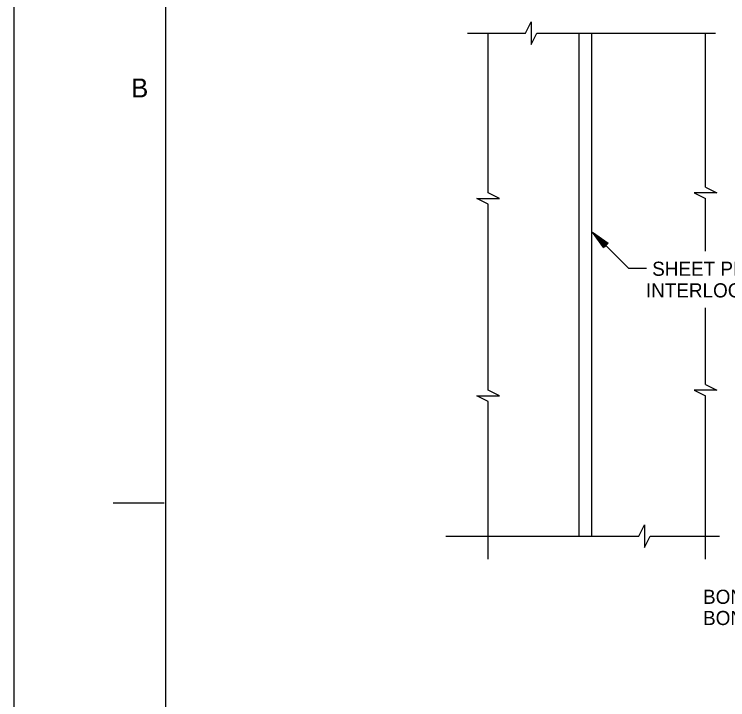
# Model space of a CAD drawing. Extents: x 22369.6 to 22428.3, y 22369.6 to 22415.
# Drawn here: x 22369.62 to 22379.05, y 22378.68 to 22387.74 of the extents above; entities that cross this region are included whole.
import ezdxf

# ---------------------------------------------------------------- set-up
doc = ezdxf.new("R2010")
doc.units = 0
for name, color, linetype in [('Level 1', 7, 'Continuous'), ('Level 10', 7, 'Continuous'), ('Level 2', 7, 'Continuous'), ('Level 3', 7, 'Continuous'), ('Level 4', 7, 'Continuous'), ('Level 9', 7, 'Continuous')]:
    doc.layers.add(name, color=color, linetype=linetype)

msp = doc.modelspace()

# ---------------------------------------------------------------- linework, layer by layer
at = {"layer": 'Level 1'}
for p, q in [((22375.6089, 22387.4886), (22376.3752, 22387.4886)), ((22375.8823, 22385.3773), (22375.8823, 22387.4886)), ((22376.5247, 22387.4886), (22378.8846, 22387.4886)), ((22378.7536, 22385.452), (22378.7536, 22387.4886)), ((22378.7536, 22384.6093), (22378.7536, 22385.3025)), ((22375.8823, 22382.7706), (22375.8823, 22385.2278)), ((22378.7536, 22382.8454), (22378.7536, 22383.86)), ((22375.8823, 22380.5372), (22375.8823, 22382.6211)), ((22378.7536, 22380.5372), (22378.7536, 22382.6959)), ((22375.3239, 22380.8406), (22377.8724, 22380.8406)), ((22378.0219, 22380.8406), (22378.9382, 22380.8406))]:
    msp.add_line(p, q, dxfattribs=at)
msp.add_lwpolyline([(22369.6213, 22414.9546), (22428.2885, 22414.9546), (22428.2885, 22369.6213), (22369.6213, 22369.6213)], close=True, dxfattribs=at)
for points in [[(22376.3752, 22387.4886), (22376.4497, 22387.6386), (22376.4497, 22387.339), (22376.5247, 22387.4886)], [(22378.7536, 22385.452), (22378.9036, 22385.3775), (22378.604, 22385.3775), (22378.7536, 22385.3025)], [(22375.8823, 22385.2278), (22375.7323, 22385.3023), (22376.032, 22385.3023), (22375.8823, 22385.3773)], [(22377.9726, 22384.3797), (22377.74, 22384.3797), (22377.261, 22384.8594)], [(22378.7536, 22382.8454), (22378.9036, 22382.7709), (22378.604, 22382.7709), (22378.7536, 22382.6959)], [(22375.8823, 22382.6211), (22375.7323, 22382.6956), (22376.032, 22382.6956), (22375.8823, 22382.7706)], [(22377.8724, 22380.8406), (22377.9469, 22380.9906), (22377.9469, 22380.6909), (22378.0219, 22380.8406)]]:
    msp.add_lwpolyline(points, dxfattribs=at)
at = {"layer": 'Level 10'}
msp.add_line((22370.9285, 22381.28), (22371.6005, 22381.28), dxfattribs=at)
at = {"layer": 'Level 2'}
for p, q in [((22377.0811, 22387.4886), (22377.0811, 22380.8406)), ((22377.2477, 22387.4886), (22377.2477, 22380.8406))]:
    msp.add_line(p, q, dxfattribs=at)
at = {"layer": 'Level 3'}
for p, q in [((22377.261, 22384.8594), (22377.261, 22384.8594)), ((22377.31, 22384.8103), (22377.31, 22384.8103))]:
    msp.add_line(p, q, dxfattribs=at)
msp.add_lwpolyline([(22377.4079, 22384.6537), (22377.261, 22384.8594), (22377.4664, 22384.7121), (22377.4164, 22384.6622), (22377.31, 22384.8103), (22377.4495, 22384.7103), (22377.4174, 22384.6782), (22377.3571, 22384.7631), (22377.4325, 22384.7084), (22377.4193, 22384.6952), (22377.4061, 22384.7141)], dxfattribs=at)
at = {"layer": 'Level 9'}
msp.add_line((22371.6213, 22370.288), (22371.6213, 22414.288), dxfattribs=at)

# ---------------------------------------------------------------- texts
at = {"layer": 'Level 1'}
msp.add_text('B', height=0.2497, dxfattribs=at).set_placement((22371.1685, 22386.64))
at = {"layer": 'Level 4'}
for s, height, p in [('SHEET PILE', 0.18667, (22378.048, 22384.2822)), (' INTERLOCKS', 0.186667, (22377.8954, 22383.9966)), ('BOND CABLE, SEE', 0.186698, (22378.7202, 22379.947)), ('BONDING NOTES DWG. X', 0.186698, (22378.7202, 22379.667))]:
    msp.add_text(s, height=height, dxfattribs=at).set_placement(p)

doc.saveas('drawing.dxf')
